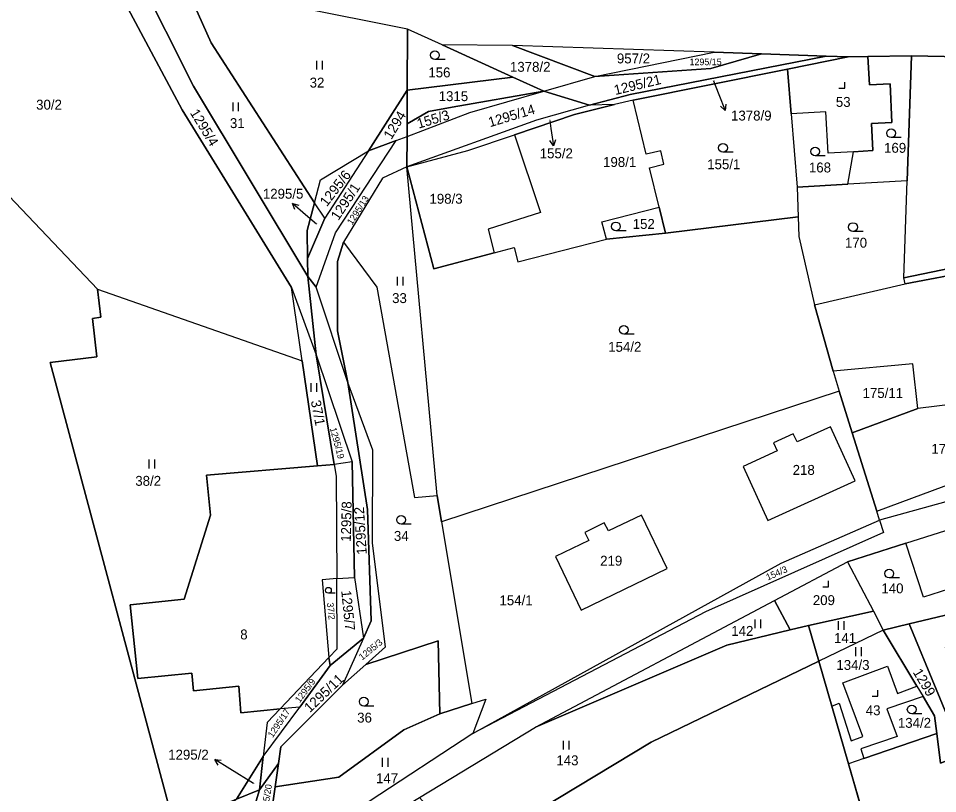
# Model space of a CAD drawing. Extents: x -588699 to -585793, y -1060280 to -1056731.
# Drawn here: x -588200.6 to -588042.9, y -1058248.3 to -1058115.3 of the extents above; entities that cross this region are included whole.
import ezdxf

# ---------------------------------------------------------------- set-up
doc = ezdxf.new("R2010")
doc.units = 0
for name, color, linetype in [('Druh pozemku', 7, 'Continuous'), ('Lesy', 7, 'Continuous'), ('Parcela nároku', 7, 'Continuous'), ('Parcelní číslo', 7, 'Continuous')]:
    doc.layers.add(name, color=color, linetype=linetype)

msp = doc.modelspace()

# ---------------------------------------------------------------- linework, layer by layer
at = {"layer": 'Druh pozemku'}
for p, q in [((-588149.47, -1058122.56), (-588149.47, -1058124.06)), ((-588148.45, -1058124.06), (-588148.45, -1058122.56)), ((-588127.39, -1058122.37), (-588129.14, -1058122.37)), ((-588163.83, -1058129.75), (-588163.83, -1058131.25)), ((-588162.81, -1058131.25), (-588162.81, -1058129.75)), ((-588049.15, -1058135.77), (-588050.9, -1058135.77)), ((-588077.98, -1058138.26), (-588079.73, -1058138.26)), ((-588062.18, -1058138.91), (-588063.93, -1058138.91)), ((-588096.34, -1058151.75), (-588098.09, -1058151.75)), ((-588055.68, -1058151.87), (-588057.43, -1058151.87)), ((-588135.63, -1058159.67), (-588135.63, -1058161.17)), ((-588134.6, -1058161.17), (-588134.6, -1058159.67)), ((-588094.99, -1058169.5), (-588096.74, -1058169.5)), ((-588150.42, -1058177.92), (-588150.42, -1058179.42)), ((-588149.4, -1058179.42), (-588149.4, -1058177.92)), ((-588178.2, -1058191.03), (-588178.2, -1058192.53)), ((-588177.18, -1058192.53), (-588177.18, -1058191.03)), ((-588133.2, -1058202.11), (-588134.95, -1058202.11)), ((-588049.46, -1058211.34), (-588051.21, -1058211.34)), ((-588146.25, -1058213.95), (-588147.42, -1058213.95)), ((-588074.27, -1058218.44), (-588074.27, -1058219.94)), ((-588073.24, -1058219.94), (-588073.24, -1058218.44)), ((-588059.96, -1058218.76), (-588059.96, -1058220.26)), ((-588058.94, -1058220.26), (-588058.94, -1058218.76)), ((-588057.02, -1058223.23), (-588057.02, -1058224.73)), ((-588055.99, -1058224.73), (-588055.99, -1058223.23)), ((-588139.61, -1058233.31), (-588141.36, -1058233.31)), ((-588045.61, -1058234.66), (-588047.36, -1058234.66)), ((-588107.12, -1058239.26), (-588107.12, -1058240.76)), ((-588106.09, -1058240.76), (-588106.09, -1058239.26)), ((-588138.2, -1058242.23), (-588138.2, -1058243.73)), ((-588137.18, -1058243.73), (-588137.18, -1058242.23))]:
    msp.add_line(p, q, dxfattribs=at)
for points in [[(-588059.85, -1058127.27), (-588058.85, -1058127.27), (-588058.85, -1058126.27)], [(-588062.63, -1058212.83), (-588061.63, -1058212.83), (-588061.63, -1058211.83)], [(-588054.17, -1058231.61), (-588053.17, -1058231.61), (-588053.17, -1058230.61)]]:
    msp.add_lwpolyline(points, dxfattribs=at)
for centre, radius in [((-588129.14, -1058121.62), 0.75), ((-588050.9, -1058135.02), 0.75), ((-588079.73, -1058137.51), 0.75), ((-588063.93, -1058138.16), 0.75), ((-588098.09, -1058151), 0.75), ((-588057.43, -1058151.12), 0.75), ((-588096.74, -1058168.75), 0.75), ((-588134.95, -1058201.36), 0.75), ((-588051.21, -1058210.59), 0.75), ((-588147.42, -1058213.45), 0.503), ((-588141.36, -1058232.56), 0.75), ((-588047.36, -1058233.91), 0.75)]:
    msp.add_circle(centre, radius, dxfattribs=at)
at = {"layer": 'Lesy'}
for p, q in [((-588063.29, -1058225.64), (-588092.05, -1058239.54)), ((-588061.07, -1058233.32), (-588063.29, -1058225.64)), ((-588058.21, -1058243.22), (-588061.07, -1058233.32)), ((-588092.05, -1058239.54), (-588120.78, -1058256.86)), ((-588051.99, -1058264.75), (-588058.21, -1058243.22))]:
    msp.add_line(p, q, dxfattribs=at)
at = {"layer": 'Parcela nároku'}
for points in [[(-588185.34, -1058106.83), (-588243.9, -1058091.45), (-588233.5, -1058111.89), (-588220.72, -1058126.38), (-588187, -1058161.78), (-588151.89, -1058174.08), (-588153.74, -1058161.51), (-588172.49, -1058131.01)], [(-588150.93, -1058159.62), (-588170.57, -1058126.95), (-588180.09, -1058107.88), (-588185.34, -1058106.83), (-588172.49, -1058131.01), (-588153.74, -1058161.51), (-588149.53, -1058173.07)], [(-588150.93, -1058159.62), (-588150.98, -1058156.5), (-588151.05, -1058151.7), (-588149.8, -1058146.94), (-588167.54, -1058119.5), (-588172.01, -1058109.5), (-588180.09, -1058107.88), (-588170.57, -1058126.95)], [(-588133.87, -1058117.14), (-588172.01, -1058109.5), (-588167.54, -1058119.5), (-588149.8, -1058146.94), (-588148.76, -1058143.01), (-588140.51, -1058138.04), (-588133.9, -1058127.64)], [(-588233.5, -1058111.89), (-588220.72, -1058126.38), (-588187, -1058161.78), (-588186.48, -1058166.56), (-588187.86, -1058166.8), (-588187.14, -1058173.38), (-588195.16, -1058174.34), (-588173.47, -1058255.38), (-588188.13, -1058265.89), (-588195.07, -1058269.17), (-588225.24, -1058292.17), (-588257.55, -1058129.34), (-588255.46, -1058125.26)], [(-588127.93, -1058119.84), (-588133.87, -1058117.14), (-588133.9, -1058127.64), (-588115.77, -1058125.38)], [(-588115.84, -1058119.95), (-588127.93, -1058119.84), (-588115.77, -1058125.38), (-588110.44, -1058127.81), (-588101.71, -1058125.28)], [(-588081.23, -1058121.1), (-588115.84, -1058119.95), (-588101.71, -1058125.28)], [(-588081.23, -1058121.1), (-588073.1, -1058121.39), (-588081.84, -1058123.91), (-588101.71, -1058125.28)], [(-588101.71, -1058125.28), (-588081.84, -1058123.91), (-588073.1, -1058121.39), (-588062.02, -1058121.79), (-588095.65, -1058128.38), (-588102.62, -1058130.2), (-588110.44, -1058127.81)], [(-588102.62, -1058130.2), (-588095.65, -1058128.38), (-588062.02, -1058121.79), (-588058.28, -1058121.93), (-588068.65, -1058124.01), (-588095.14, -1058129.32), (-588098.33, -1058130.1)], [(-588068.65, -1058124.01), (-588058.28, -1058121.93), (-588054.87, -1058121.87), (-588054.61, -1058126.71), (-588051.08, -1058126.53), (-588050.75, -1058133.15), (-588054.26, -1058133.34), (-588054.02, -1058138), (-588057.33, -1058138.19), (-588061.69, -1058138.43), (-588062.08, -1058131.35), (-588068.03, -1058131.7)], [(-588057.33, -1058138.19), (-588054.02, -1058138), (-588054.26, -1058133.34), (-588050.75, -1058133.15), (-588051.08, -1058126.53), (-588054.61, -1058126.71), (-588054.87, -1058121.87), (-588047.38, -1058121.73), (-588048.14, -1058143.2), (-588058.32, -1058143.78)], [(-588014.55, -1058132.08), (-588011.42, -1058152.1), (-588048.73, -1058159.83), (-588048.14, -1058143.2), (-588047.38, -1058121.73), (-588036.18, -1058121.95), (-588035.78, -1058134.31), (-588019, -1058133.7), (-588019.05, -1058132.15)], [(-588068.03, -1058131.7), (-588067.02, -1058144.27), (-588066.83, -1058149.38), (-588089.59, -1058152.16), (-588090.68, -1058147.69), (-588092.32, -1058140.93), (-588089.88, -1058140.34), (-588090.39, -1058138.01), (-588092.88, -1058138.62), (-588095.14, -1058129.32), (-588068.65, -1058124.01)], [(-588133.9, -1058127.64), (-588133.92, -1058133.42), (-588130.26, -1058131.29), (-588126.19, -1058130.55), (-588110.44, -1058127.81), (-588115.77, -1058125.38)], [(-588133.9, -1058127.64), (-588140.51, -1058138.04), (-588135.79, -1058136.25), (-588133.93, -1058135.55), (-588133.92, -1058133.42)], [(-588110.44, -1058127.81), (-588102.62, -1058130.2), (-588111.73, -1058132.78), (-588133.94, -1058140.8), (-588133.93, -1058135.55), (-588123.15, -1058131.48)], [(-588130.26, -1058131.29), (-588133.92, -1058133.42), (-588133.93, -1058135.55), (-588123.15, -1058131.48), (-588110.44, -1058127.81), (-588126.19, -1058130.55)], [(-588111.73, -1058132.78), (-588133.94, -1058140.8), (-588123.52, -1058137.98), (-588115.47, -1058135.26), (-588105.22, -1058131.79), (-588098.33, -1058130.1), (-588102.62, -1058130.2)], [(-588111.03, -1058148.59), (-588120.03, -1058151.48), (-588118.99, -1058155.51), (-588115.55, -1058154.61), (-588114.9, -1058157.06), (-588099.72, -1058153.2), (-588100.5, -1058150.22), (-588090.68, -1058147.69), (-588092.32, -1058140.93), (-588089.88, -1058140.34), (-588090.39, -1058138.01), (-588092.88, -1058138.62), (-588095.14, -1058129.32), (-588098.33, -1058130.1), (-588105.22, -1058131.79), (-588115.47, -1058135.26)], [(-588062.08, -1058131.35), (-588068.03, -1058131.7), (-588067.02, -1058144.27), (-588058.32, -1058143.78), (-588057.33, -1058138.19), (-588061.69, -1058138.43)], [(-588115.47, -1058135.26), (-588111.03, -1058148.59), (-588120.03, -1058151.48), (-588118.99, -1058155.51), (-588129.34, -1058158.28), (-588133.94, -1058140.8), (-588123.52, -1058137.98)], [(-588148.01, -1058149.57), (-588150.98, -1058156.5), (-588150.93, -1058159.62), (-588149.51, -1058161.45), (-588146.19, -1058152.13), (-588135.79, -1058136.25), (-588140.51, -1058138.04)], [(-588149.51, -1058161.45), (-588146.19, -1058152.13), (-588135.79, -1058136.25), (-588133.93, -1058135.55), (-588133.94, -1058140.8), (-588138.16, -1058142.74), (-588144.81, -1058153.73), (-588145.88, -1058157.01), (-588145.88, -1058168.9), (-588144.07, -1058177.78)], [(-588148.76, -1058143.01), (-588140.51, -1058138.04), (-588148.01, -1058149.57), (-588149.8, -1058146.94)], [(-588138.16, -1058142.74), (-588144.81, -1058153.73), (-588139.11, -1058161.44), (-588132.62, -1058197.53), (-588128.76, -1058197.17), (-588133.94, -1058140.8)], [(-588114.9, -1058157.06), (-588099.72, -1058153.2), (-588089.59, -1058152.16), (-588066.83, -1058149.38), (-588066.7, -1058152.74), (-588064.06, -1058164.47), (-588060.82, -1058175.82), (-588059.83, -1058179.29), (-588128.01, -1058201.69), (-588128.76, -1058197.17), (-588133.94, -1058140.8), (-588129.34, -1058158.28), (-588118.99, -1058155.51), (-588115.55, -1058154.61)], [(-588058.32, -1058143.78), (-588067.02, -1058144.27), (-588066.83, -1058149.38), (-588066.7, -1058152.74), (-588064.06, -1058164.47), (-588048.49, -1058160.86), (-588048.73, -1058159.83), (-588048.14, -1058143.2)], [(-588148.01, -1058149.57), (-588149.8, -1058146.94), (-588151.05, -1058151.7), (-588150.98, -1058156.5)], [(-588100.5, -1058150.22), (-588090.68, -1058147.69), (-588089.59, -1058152.16), (-588099.72, -1058153.2)], [(-588011.42, -1058152.1), (-588010.91, -1058153.75), (-588036.97, -1058158.68), (-588048.49, -1058160.86), (-588048.73, -1058159.83)], [(-588132.62, -1058197.53), (-588128.76, -1058197.17), (-588128.01, -1058201.69), (-588122.82, -1058232.88), (-588128.29, -1058234.64), (-588128.57, -1058222.1), (-588141, -1058226.16), (-588137.65, -1058223.16), (-588139.88, -1058205.36), (-588139.82, -1058189.42), (-588144.07, -1058177.78), (-588145.88, -1058168.9), (-588145.88, -1058157.01), (-588144.81, -1058153.73), (-588139.11, -1058161.44)], [(-588036.97, -1058158.68), (-588031.79, -1058172.85), (-588007.07, -1058168.5), (-588006.42, -1058171.01), (-588005.12, -1058185.1), (-588024.21, -1058189.07), (-588007.87, -1058184.23), (-588009.65, -1058175.86), (-588026.28, -1058179.79), (-588046.31, -1058182.23), (-588047.18, -1058174.61), (-588060.82, -1058175.82), (-588064.06, -1058164.47), (-588048.49, -1058160.86)], [(-588140.09, -1058218.7), (-588140.69, -1058199.57), (-588144.07, -1058177.78), (-588149.51, -1058161.45), (-588150.93, -1058159.62), (-588149.53, -1058173.07), (-588143.35, -1058191.39), (-588142.96, -1058211.24), (-588141.4, -1058221.64)], [(-588180.1, -1058228.59), (-588170.87, -1058227.65), (-588170.56, -1058230.7), (-588162.79, -1058229.9), (-588162.42, -1058234.46), (-588155.71, -1058233.81), (-588157.93, -1058236.15), (-588158.6, -1058241.95), (-588163.19, -1058249.31), (-588167.5, -1058251.1), (-588173.47, -1058255.38), (-588195.16, -1058174.34), (-588187.14, -1058173.38), (-588187.86, -1058166.8), (-588186.48, -1058166.56), (-588187, -1058161.78), (-588151.89, -1058174.08), (-588149.31, -1058192.11), (-588168.34, -1058193.67), (-588167.64, -1058200.58), (-588172.15, -1058214.97), (-588181.43, -1058215.92)], [(-588153.74, -1058161.51), (-588149.53, -1058173.07), (-588146.42, -1058191.87), (-588149.31, -1058192.11), (-588151.89, -1058174.08)], [(-588149.53, -1058173.07), (-588143.35, -1058191.39), (-588146.42, -1058191.87)], [(-588046.31, -1058182.23), (-588047.18, -1058174.61), (-588060.82, -1058175.82), (-588059.83, -1058179.29), (-588057.57, -1058186.43)], [(-588139.82, -1058189.42), (-588144.07, -1058177.78), (-588140.69, -1058199.57), (-588140.09, -1058218.7), (-588141.4, -1058221.64), (-588145.02, -1058229.76), (-588141, -1058226.16), (-588137.65, -1058223.16), (-588139.88, -1058205.36)], [(-588120.43, -1058232.13), (-588122.62, -1058238.02), (-588069.74, -1058208.82), (-588052.9, -1058201.43), (-588053.33, -1058199.85), (-588057.57, -1058186.43), (-588059.83, -1058179.29), (-588128.01, -1058201.69), (-588122.82, -1058232.88)], [(-588024.21, -1058189.07), (-588026.28, -1058179.79), (-588046.31, -1058182.23), (-588057.57, -1058186.43), (-588053.33, -1058199.85)], [(-588070.46, -1058189.5), (-588076.27, -1058192.23), (-588072.05, -1058201.48), (-588057.06, -1058194.65), (-588061.28, -1058185.39), (-588067.03, -1058187.98), (-588067.68, -1058186.61), (-588071.08, -1058188.12)], [(-588076.27, -1058192.23), (-588072.05, -1058201.48), (-588057.06, -1058194.65), (-588061.28, -1058185.39), (-588067.03, -1058187.98), (-588067.68, -1058186.61), (-588071.08, -1058188.12), (-588070.46, -1058189.5)], [(-588024.21, -1058189.07), (-588023.22, -1058193.36), (-588026.8, -1058194.23), (-588052.9, -1058201.43), (-588053.33, -1058199.85)], [(-588149.31, -1058192.11), (-588146.42, -1058191.87), (-588146.1, -1058193.84), (-588145.99, -1058211.43), (-588148.46, -1058211.63), (-588147.36, -1058225), (-588150.52, -1058228.34), (-588155.71, -1058233.81), (-588162.42, -1058234.46), (-588162.79, -1058229.9), (-588170.56, -1058230.7), (-588170.87, -1058227.65), (-588180.1, -1058228.59), (-588181.43, -1058215.92), (-588172.15, -1058214.97), (-588167.64, -1058200.58), (-588168.34, -1058193.67)], [(-588142.96, -1058211.24), (-588143.35, -1058191.39), (-588146.42, -1058191.87), (-588146.1, -1058193.84), (-588145.99, -1058211.43)], [(-588048.39, -1058205.39), (-588029.03, -1058199.24), (-588025.28, -1058210.8), (-588030.46, -1058212.46), (-588037.44, -1058214.7), (-588038.19, -1058212.33), (-588045.35, -1058214.64)], [(-588069.74, -1058208.82), (-588052.9, -1058201.43), (-588052.21, -1058203.52), (-588082.74, -1058217.13), (-588122.62, -1058238.02)], [(-588100.11, -1058201.89), (-588103.44, -1058203.53), (-588102.76, -1058204.91), (-588108.46, -1058207.64), (-588104.05, -1058216.84), (-588089.31, -1058209.73), (-588093.71, -1058200.53), (-588099.35, -1058203.23)], [(-588108.46, -1058207.64), (-588104.05, -1058216.84), (-588089.31, -1058209.73), (-588093.71, -1058200.53), (-588099.35, -1058203.23), (-588100.11, -1058201.89), (-588103.44, -1058203.53), (-588102.76, -1058204.91)], [(-588037.44, -1058214.7), (-588038.19, -1058212.33), (-588045.35, -1058214.64), (-588048.39, -1058205.39), (-588058.38, -1058208.56), (-588053.92, -1058217.06), (-588052.23, -1058220.29), (-588047.8, -1058219.23), (-588036.77, -1058216.58), (-588032.79, -1058215.62), (-588029.61, -1058214.86), (-588030.46, -1058212.46)], [(-588070.92, -1058215.21), (-588058.38, -1058208.56), (-588053.92, -1058217.06), (-588065.07, -1058219.48), (-588068.21, -1058220.23)], [(-588145.92, -1058223.48), (-588145.99, -1058211.43), (-588148.46, -1058211.63), (-588147.36, -1058225)], [(-588142.96, -1058211.24), (-588141.4, -1058221.64), (-588147.1, -1058226.37), (-588147.36, -1058225), (-588145.92, -1058223.48), (-588145.99, -1058211.43)], [(-588070.92, -1058215.21), (-588068.21, -1058220.23), (-588079.08, -1058222.84), (-588111.87, -1058236.93)], [(-588032.03, -1058217.82), (-588032.79, -1058215.62), (-588036.77, -1058216.58), (-588036.38, -1058218.14), (-588035.49, -1058221.71), (-588032.53, -1058220.95), (-588029.94, -1058231.14), (-588028.28, -1058237.68), (-588038.53, -1058241.64), (-588042.41, -1058243.13), (-588043.06, -1058238.01), (-588055.57, -1058242.31), (-588058.21, -1058243.22), (-588051.99, -1058264.75), (-588051.6, -1058266.1), (-588042.29, -1058259.76), (-588019.94, -1058256.55), (-588010.93, -1058249.05), (-588005.9, -1058234.96), (-588005.42, -1058222.88), (-588013.42, -1058225.65), (-588027.07, -1058229.5), (-588029.61, -1058220.15), (-588031.08, -1058220.59)], [(-588053.92, -1058217.06), (-588052.23, -1058220.29), (-588063.29, -1058225.64), (-588065.07, -1058219.48)], [(-588039.93, -1058229.55), (-588041.56, -1058223.26), (-588039.19, -1058222.65), (-588040.1, -1058219.07), (-588036.38, -1058218.14), (-588036.77, -1058216.58), (-588047.8, -1058219.23), (-588038.53, -1058241.64), (-588028.28, -1058237.68), (-588029.94, -1058231.14), (-588036.59, -1058232.86), (-588037.58, -1058228.95)], [(-588065.07, -1058219.48), (-588063.29, -1058225.64), (-588092.05, -1058239.54), (-588120.78, -1058256.86), (-588122.86, -1058254.52), (-588126.94, -1058249.92), (-588129.42, -1058251.63), (-588131.81, -1058249.01), (-588111.87, -1058236.93), (-588079.08, -1058222.84), (-588068.21, -1058220.23)], [(-588055.72, -1058238.52), (-588059.19, -1058229.35), (-588051.49, -1058226.46), (-588049.78, -1058231.15), (-588046.46, -1058229.93), (-588052.23, -1058220.29), (-588063.29, -1058225.64), (-588061.07, -1058233.32), (-588059.79, -1058232.8), (-588057.74, -1058239.26)], [(-588047.8, -1058219.23), (-588052.23, -1058220.29), (-588046.46, -1058229.93), (-588045.41, -1058231.69), (-588043.44, -1058234.98), (-588043.06, -1058238.01), (-588042.41, -1058243.13), (-588038.53, -1058241.64)], [(-588158.6, -1058241.95), (-588152.34, -1058233.52), (-588147.1, -1058226.37), (-588141.4, -1058221.64), (-588145.02, -1058229.76), (-588155.55, -1058240.29), (-588155.97, -1058243.19), (-588159.26, -1058247.68)], [(-588155.55, -1058240.29), (-588145.02, -1058229.76), (-588141, -1058226.16), (-588128.57, -1058222.1), (-588128.29, -1058234.64), (-588134.5, -1058237.4), (-588145.64, -1058245.51), (-588156.55, -1058247.18), (-588155.97, -1058243.19)], [(-588155.71, -1058233.81), (-588150.52, -1058228.34), (-588147.36, -1058225), (-588147.1, -1058226.37), (-588152.34, -1058233.52)], [(-588142.99, -1058277), (-588134.96, -1058270.82), (-588135.69, -1058269.22), (-588127.72, -1058261.45), (-588120.78, -1058256.86), (-588092.05, -1058239.54), (-588063.29, -1058225.64), (-588061.07, -1058233.32), (-588058.21, -1058243.22), (-588051.99, -1058264.75), (-588091.44, -1058255.97), (-588138.95, -1058307.8), (-588146.99, -1058325.07), (-588157.01, -1058313.06), (-588150.15, -1058308.19), (-588149.06, -1058306.32), (-588148.16, -1058304.94), (-588142.9, -1058301.14), (-588140.46, -1058304.51), (-588135.34, -1058300.83), (-588137.79, -1058297.45), (-588133.2, -1058294.13), (-588139.05, -1058286.04)], [(-588051.62, -1058233.81), (-588049.83, -1058238.55), (-588056.11, -1058240.65), (-588055.57, -1058242.31), (-588058.21, -1058243.22), (-588061.07, -1058233.32), (-588059.79, -1058232.8), (-588057.74, -1058239.26), (-588055.72, -1058238.52), (-588059.19, -1058229.35), (-588051.49, -1058226.46), (-588049.78, -1058231.15), (-588046.46, -1058229.93), (-588045.41, -1058231.69)], [(-588157.37, -1058252.85), (-588156.55, -1058247.18), (-588145.64, -1058245.51), (-588134.5, -1058237.4), (-588128.29, -1058234.64), (-588122.82, -1058232.88), (-588120.43, -1058232.13), (-588122.62, -1058238.02), (-588140.45, -1058249.69), (-588152.13, -1058253.84)], [(-588043.44, -1058234.98), (-588045.41, -1058231.69), (-588051.62, -1058233.81), (-588049.83, -1058238.55), (-588056.11, -1058240.65), (-588055.57, -1058242.31), (-588043.06, -1058238.01)], [(-588152.34, -1058233.52), (-588155.71, -1058233.81), (-588157.93, -1058236.15), (-588158.6, -1058241.95)], [(-588163.19, -1058249.31), (-588158.6, -1058241.95), (-588159.26, -1058247.68)], [(-588159.26, -1058247.68), (-588155.97, -1058243.19), (-588156.55, -1058247.18), (-588157.37, -1058252.85), (-588161.37, -1058254.66)], [(-588163.19, -1058249.31), (-588159.26, -1058247.68), (-588161.37, -1058254.66), (-588170.17, -1058260.23), (-588188.82, -1058270.29), (-588195.18, -1058273.49), (-588236.69, -1058310.21), (-588240.57, -1058313.64), (-588267.55, -1058333.34), (-588279.64, -1058340.05), (-588283.85, -1058339.62), (-588270.15, -1058331.48), (-588250.18, -1058316.69), (-588246.95, -1058314.3), (-588231.71, -1058301.52), (-588195.07, -1058269.17), (-588188.13, -1058265.89), (-588172.92, -1058257.42), (-588171.55, -1058256.65)]]:
    msp.add_lwpolyline(points, close=True, dxfattribs=at)
for points in [[(-587879.59, -1058109.01), (-587910.22, -1058119.99), (-587919.57, -1058124.47), (-587933.06, -1058125.98), (-587949.07, -1058127.46), (-587960.12, -1058126.1), (-587971.04, -1058124.84), (-587973.98, -1058124.5), (-587981.13, -1058122.84), (-588005.14, -1058122.81), (-588014.09, -1058122.32), (-588016.07, -1058122.34), (-588019.38, -1058122.28), (-588036.18, -1058121.95), (-588047.38, -1058121.73), (-588054.87, -1058121.87), (-588058.28, -1058121.93), (-588062.02, -1058121.79), (-588073.1, -1058121.39), (-588081.23, -1058121.1), (-588115.84, -1058119.95), (-588127.93, -1058119.84), (-588133.87, -1058117.14), (-588172.01, -1058109.5)], [(-588026.8, -1058194.23), (-588052.9, -1058201.43), (-588052.21, -1058203.52), (-588082.74, -1058217.13), (-588122.62, -1058238.02), (-588140.45, -1058249.69), (-588152.13, -1058253.84), (-588157.37, -1058252.85), (-588161.37, -1058254.66), (-588170.17, -1058260.23), (-588160.2, -1058257.29), (-588151.54, -1058257.82), (-588146.11, -1058257.12), (-588144.26, -1058256.44), (-588142.05, -1058255.22), (-588137.93, -1058252.72), (-588131.81, -1058249.01), (-588111.87, -1058236.93), (-588070.92, -1058215.21), (-588058.38, -1058208.56), (-588048.39, -1058205.39), (-588029.03, -1058199.24)]]:
    msp.add_lwpolyline(points, dxfattribs=at)
at = {"layer": 'Parcelní číslo'}
for p, q in [((-588081.38, -1058126), (-588080.45, -1058128.34)), ((-588080.45, -1058128.34), (-588079.35, -1058131.13)), ((-588109.44, -1058132.81), (-588109.24, -1058134.21)), ((-588109.24, -1058134.21), (-588108.82, -1058137.18)), ((-588151.33, -1058149.02), (-588153.59, -1058147.05)), ((-588149.48, -1058150.64), (-588151.33, -1058149.02)), ((-588164.35, -1058244.08), (-588166.9, -1058242.51)), ((-588160.24, -1058246.61), (-588164.35, -1058244.08))]:
    msp.add_line(p, q, dxfattribs=at)
for points in [[(-588079.25, -1058130.02), (-588079.35, -1058131.13), (-588080.18, -1058130.38)], [(-588108.46, -1058136.12), (-588108.82, -1058137.18), (-588109.45, -1058136.26)], [(-588153.17, -1058148.08), (-588153.59, -1058147.05), (-588152.51, -1058147.33)], [(-588166.32, -1058243.46), (-588166.9, -1058242.51), (-588165.79, -1058242.61)]]:
    msp.add_lwpolyline(points, dxfattribs=at)

# ---------------------------------------------------------------- texts
at = {"layer": 'Parcela nároku'}
for s, height, p in [('957/2', 1.7, (-588097.93, -1058123.03)), ('1295/15', 1.14, (-588085.47, -1058123.34)), ('156', 1.7, (-588130.27, -1058125.43)), ('1378/2', 1.7, (-588116.27, -1058124.47)), ('32', 1.7, (-588150.63, -1058127.17)), ('1378/9', 0.1, (-588081.58, -1058126)), ('1315', 1.7, (-588128.5, -1058129.5)), ('53', 1.7, (-588060.37, -1058130.49)), ('30/2', 1.7, (-588197.55, -1058130.96)), ('31', 1.7, (-588164.31, -1058134.13)), ('155/2', 0.1, (-588109.61, -1058132.81)), ('169', 1.7, (-588052.1, -1058138.37)), ('198/1', 1.7, (-588100.3, -1058140.8)), ('155/1', 1.7, (-588082.44, -1058141.19)), ('168', 1.7, (-588064.99, -1058141.74)), ('198/3', 1.7, (-588130.08, -1058147.11)), ('1295/5', 0.1, (-588149.68, -1058150.64)), ('152', 1.7, (-588095.22, -1058151.43)), ('170', 1.7, (-588058.81, -1058154.65)), ('33', 1.7, (-588136.49, -1058164.16)), ('154/2', 1.7, (-588099.42, -1058172.52)), ('175/11', 1.7, (-588055.79, -1058180.45)), ('175/10', 1.7, (-588043.99, -1058190.03)), ('218', 1.7, (-588067.78, -1058193.64)), ('38/2', 1.7, (-588180.54, -1058195.52)), ('34', 1.7, (-588136.18, -1058204.97)), ('219', 1.7, (-588100.8, -1058209.23)), ('140', 1.7, (-588052.56, -1058213.97)), ('154/1', 1.7, (-588118.07, -1058216.02)), ('209', 1.7, (-588064.32, -1058215.99)), ('8', 1.7, (-588162.54, -1058221.88)), ('142', 1.7, (-588078.31, -1058221.27)), ('141', 1.7, (-588060.68, -1058222.49)), ('134/3', 1.7, (-588060.28, -1058227.11)), ('36', 1.7, (-588142.48, -1058236.15)), ('43', 1.7, (-588055.24, -1058234.89)), ('134/2', 1.7, (-588049.73, -1058237.05)), ('143', 1.7, (-588108.31, -1058243.48)), ('147', 1.7, (-588139.24, -1058246.56)), ('1295/2', 0.1, (-588160.45, -1058246.61))]:
    msp.add_text(s, height=height, dxfattribs=at).set_placement(p)
for s, height, rotation, p in [('1295/21', 1.7, 13.6391, (-588098.2, -1058128.47)), ('1295/14', 1.7, 16.7403, (-588119.7, -1058133.99)), ('1295/4', 1.7, 301.3934, (-588171.23, -1058131.5)), ('1294', 1.7, 58.853, (-588136.62, -1058136.21)), ('155/3', 1.7, 16.8235, (-588131.93, -1058134.24)), ('1295/6', 1.7, 52.3318, (-588147.68, -1058147.71)), ('1295/1', 1.7, 56.4966, (-588145.7, -1058150.1)), ('1295/13', 1.14, 57.5081, (-588143.35, -1058150.84)), ('37/1', 1.7, 280.8018, (-588150.44, -1058180.98)), ('1295/19', 1.14, 284.9315, (-588147.17, -1058185.67)), ('1295/8', 1.7, 88.676, (-588143.58, -1058205.15)), ('1295/12', 1.7, 93.4737, (-588140.83, -1058207.28)), ('154/3', 1.14, 23.5859, (-588072.05, -1058211.79)), ('1295/7', 1.7, 275.8639, (-588145.22, -1058213.54)), ('37/2', 1.14, 276.1444, (-588147.68, -1058215.61)), ('1295/3', 1.14, 38.9757, (-588141.63, -1058225.52)), ('1295/11', 1.7, 43.6144, (-588150.59, -1058234.54)), ('1299', 1.7, 300.744, (-588047.22, -1058227.51)), ('1295/9', 1.14, 53.1437, (-588152.34, -1058232.86)), ('1295/17', 1.14, 56.1599, (-588156.97, -1058238.85)), ('1295/20', 1.14, 80.9037, (-588157.95, -1058252.27))]:
    msp.add_text(s, height=height, rotation=rotation, dxfattribs=at).set_placement(p)
at = {"layer": 'Parcelní číslo'}
for s, p in [('1378/9', (-588078.35, -1058132.83)), ('155/2', (-588111.17, -1058139.31)), ('1295/5', (-588158.66, -1058146.25)), ('1295/2', (-588174.9, -1058242.51))]:
    msp.add_text(s, height=1.7, dxfattribs=at).set_placement(p)

doc.saveas('drawing.dxf')
